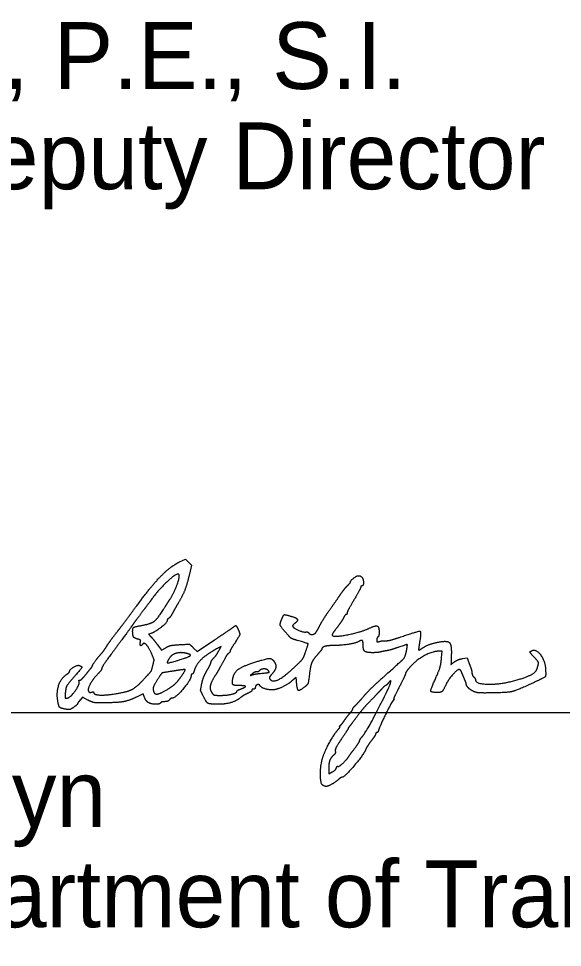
# Model space of a CAD drawing. Extents: x 0 to 34, y 0 to 22.
# Drawn here: x 25.662 to 26.8, y 6.888 to 8.834 of the extents above; entities that cross this region are included whole.
import ezdxf

# ---------------------------------------------------------------- set-up
doc = ezdxf.new("R2010")
doc.units = 0
for name, color, linetype in [('Default', 7, 'Continuous'), ('SH_Data', 7, 'Continuous'), ('SH_Text', 7, 'Continuous')]:
    doc.layers.add(name, color=color, linetype=linetype)

msp = doc.modelspace()

# ---------------------------------------------------------------- linework, layer by layer
at = {"layer": 'Default'}
for points in [[(25.9984, 7.6954), (26.011, 7.7013), (26.0174, 7.6949), (26.0237, 7.6885), (26.0193, 7.6699)], [(25.9385, 7.5455), (25.9335, 7.5439), (25.9386, 7.5387)], [(26.0274, 7.5158), (26.0356, 7.5081), (26.0718, 7.5322)], [(25.9523, 7.5221), (25.9608, 7.5105), (25.9696, 7.5158)], [(26.0813, 7.5105), (26.0858, 7.5184), (26.0803, 7.5155)], [(26.5472, 7.4946), (26.5487, 7.5084), (26.5408, 7.5084)], [(26.591, 7.493), (26.6007, 7.4945), (26.6058, 7.4809)], [(26.2431, 7.4468), (26.2424, 7.4536), (26.2365, 7.4485)], [(25.9255, 7.4112), (25.9221, 7.4192), (25.9083, 7.4124)], [(25.8068, 7.4062), (25.7953, 7.4119), (25.7903, 7.4061)], [(26.3108, 7.2607), (26.3108, 7.2513), (26.3184, 7.2556)]]:
    msp.add_lwpolyline(points, dxfattribs=at)
for points in [[(25.9088, 7.6035), (25.9385, 7.6441), (25.9803, 7.687), (25.9984, 7.6954)], [(25.9969, 7.6696), (25.9933, 7.6733), (25.9547, 7.6376), (25.9394, 7.6163)], [(25.9786, 7.6176), (25.9881, 7.6325), (26, 7.6665), (25.9969, 7.6696)], [(26.0193, 7.6699), (26.0143, 7.6487), (26.0052, 7.6251), (25.9957, 7.6092)], [(26.3564, 7.6535), (26.3564, 7.6563), (26.3696, 7.6666), (26.3733, 7.6667)], [(26.3733, 7.6667), (26.3754, 7.6667), (26.3784, 7.6655), (26.3799, 7.6639)], [(26.3498, 7.6454), (26.3535, 7.649), (26.3564, 7.6527), (26.3564, 7.6535)], [(26.3799, 7.6639), (26.3834, 7.6604), (26.3838, 7.6452), (26.3804, 7.6452)], [(26.3144, 7.5972), (26.3224, 7.6084), (26.3321, 7.6223), (26.336, 7.6282)], [(26.336, 7.6282), (26.34, 7.634), (26.3462, 7.6418), (26.3498, 7.6454)], [(26.378, 7.6427), (26.378, 7.6413), (26.3715, 7.6292), (26.3636, 7.6158)], [(26.3804, 7.6452), (26.3791, 7.6452), (26.378, 7.644), (26.378, 7.6427)], [(25.9394, 7.6163), (25.9358, 7.6113), (25.9263, 7.5986), (25.9184, 7.5881)], [(25.9681, 7.6009), (25.9714, 7.6061), (25.9761, 7.6136), (25.9786, 7.6176)], [(25.9957, 7.6092), (25.9922, 7.6032), (25.987, 7.5941), (25.9842, 7.5888)], [(26.3636, 7.6158), (26.3557, 7.6024), (26.3492, 7.59), (26.3492, 7.5883)], [(25.8687, 7.5501), (25.8776, 7.5614), (25.8956, 7.5855), (25.9088, 7.6035)], [(25.9183, 7.5623), (25.9389, 7.566), (25.953, 7.5769), (25.9681, 7.6009)], [(25.9842, 7.5888), (25.9813, 7.5835), (25.9775, 7.5783), (25.9757, 7.5773)], [(26.293, 7.5636), (26.2969, 7.5708), (26.3065, 7.586), (26.3144, 7.5972)], [(26.3492, 7.5883), (26.3492, 7.5866), (26.3483, 7.5852), (26.3472, 7.5852)], [(25.9184, 7.5881), (25.9105, 7.5777), (25.9024, 7.5667), (25.9004, 7.5637)], [(25.9724, 7.5718), (25.9724, 7.5681), (25.9467, 7.5481), (25.9385, 7.5455)], [(25.9757, 7.5773), (25.9739, 7.5762), (25.9724, 7.5738), (25.9724, 7.5718)], [(26.2222, 7.546), (26.2106, 7.5591), (26.2084, 7.5658), (26.2124, 7.5754)], [(26.2124, 7.5754), (26.2161, 7.5845), (26.2192, 7.5855), (26.232, 7.5817)], [(26.232, 7.5817), (26.2439, 7.5782), (26.2468, 7.572), (26.2391, 7.5662)], [(26.342, 7.5786), (26.3402, 7.5749), (26.3341, 7.5659), (26.3284, 7.5584)], [(26.3472, 7.5852), (26.3461, 7.5852), (26.3438, 7.5822), (26.342, 7.5786)], [(25.8471, 7.5207), (25.8501, 7.5255), (25.8598, 7.5388), (25.8687, 7.5501)], [(25.9004, 7.5637), (25.8984, 7.5607), (25.8831, 7.5398), (25.8663, 7.5171)], [(25.9004, 7.5501), (25.9004, 7.557), (25.9045, 7.5598), (25.9183, 7.5623)], [(25.9114, 7.5337), (25.9042, 7.5355), (25.9004, 7.5412), (25.9004, 7.5501)], [(26.0718, 7.5322), (26.0917, 7.5455), (26.1093, 7.5574), (26.1109, 7.5588)], [(26.1109, 7.5588), (26.1155, 7.5625), (26.1178, 7.5617), (26.1208, 7.5551)], [(26.1208, 7.5551), (26.1252, 7.5454), (26.1243, 7.5413), (26.114, 7.5255)], [(26.2391, 7.5662), (26.2364, 7.5641), (26.2349, 7.5613), (26.2359, 7.5599)], [(26.2359, 7.5599), (26.2386, 7.5561), (26.2585, 7.5479), (26.2631, 7.5487)], [(26.2838, 7.5474), (26.2851, 7.549), (26.2892, 7.5563), (26.293, 7.5636)], [(26.3284, 7.5584), (26.3227, 7.5509), (26.318, 7.5437), (26.318, 7.5423)], [(26.318, 7.5423), (26.318, 7.537), (26.3776, 7.548), (26.3956, 7.5565)], [(26.3956, 7.5565), (26.4086, 7.5627), (26.4164, 7.5596), (26.4164, 7.5482)], [(26.4588, 7.5375), (26.4991, 7.5513), (26.5051, 7.5497), (26.5009, 7.5258)], [(25.9165, 7.5275), (25.9174, 7.531), (25.9162, 7.5325), (25.9114, 7.5337)], [(25.9386, 7.5387), (25.9414, 7.5359), (25.9476, 7.5284), (25.9523, 7.5221)], [(26.2456, 7.5309), (26.2349, 7.534), (26.2299, 7.5371), (26.2222, 7.546)], [(26.2624, 7.5071), (26.2681, 7.5239), (26.2677, 7.5245), (26.2456, 7.5309)], [(26.2631, 7.5487), (26.2653, 7.5491), (26.2679, 7.5483), (26.2688, 7.5469)], [(26.2688, 7.5469), (26.2709, 7.5434), (26.2809, 7.5437), (26.2838, 7.5474)], [(26.3828, 7.523), (26.3828, 7.5304), (26.3791, 7.5319), (26.3714, 7.5277)], [(26.414, 7.5384), (26.4127, 7.5376), (26.4116, 7.5347), (26.4116, 7.5321)], [(26.4116, 7.5321), (26.4116, 7.5282), (26.4126, 7.5276), (26.417, 7.529)], [(26.4164, 7.5482), (26.4164, 7.5436), (26.4153, 7.5392), (26.414, 7.5384)], [(26.417, 7.529), (26.42, 7.5299), (26.4258, 7.5306), (26.43, 7.5304)], [(26.43, 7.5304), (26.4341, 7.5303), (26.4471, 7.5334), (26.4588, 7.5375)], [(25.8308, 7.4988), (25.8374, 7.5062), (25.8417, 7.5119), (25.8471, 7.5207)], [(25.8663, 7.5171), (25.8495, 7.4945), (25.8357, 7.4744), (25.8356, 7.4724)], [(25.9208, 7.5227), (25.9184, 7.5188), (25.9152, 7.5224), (25.9165, 7.5275)], [(25.9396, 7.5041), (25.9335, 7.5178), (25.9237, 7.5274), (25.9208, 7.5227)], [(25.9696, 7.5158), (25.9761, 7.5196), (25.9837, 7.5213), (25.9988, 7.5222)], [(25.9988, 7.5222), (26.0192, 7.5234), (26.0193, 7.5233), (26.0274, 7.5158)], [(26.0803, 7.5155), (26.0569, 7.503), (26.0341, 7.4823), (26.03, 7.4698)], [(26.0685, 7.4924), (26.074, 7.4983), (26.0765, 7.5019), (26.0813, 7.5105)], [(26.114, 7.5255), (26.1087, 7.5173), (26.1044, 7.5097), (26.1044, 7.5086)], [(26.2964, 7.5132), (26.2964, 7.5123), (26.2922, 7.5069), (26.2871, 7.5012)], [(26.3207, 7.5204), (26.3092, 7.5204), (26.2964, 7.5166), (26.2964, 7.5132)], [(26.3714, 7.5277), (26.3658, 7.5248), (26.3356, 7.5204), (26.3207, 7.5204)], [(26.4021, 7.5054), (26.3897, 7.5054), (26.3828, 7.5117), (26.3828, 7.523)], [(26.4292, 7.4579), (26.4647, 7.4894), (26.4716, 7.4976), (26.474, 7.5108)], [(26.4534, 7.5155), (26.4456, 7.5128), (26.436, 7.5101), (26.432, 7.5094)], [(26.474, 7.5108), (26.4761, 7.5223), (26.4744, 7.5227), (26.4534, 7.5155)], [(26.5009, 7.5258), (26.4996, 7.5182), (26.4989, 7.5116), (26.4993, 7.5111)], [(26.4993, 7.5111), (26.4998, 7.5106), (26.5032, 7.5124), (26.5069, 7.515)], [(26.5069, 7.515), (26.5141, 7.52), (26.5324, 7.5263), (26.546, 7.5285)], [(26.546, 7.5285), (26.5607, 7.5308), (26.5683, 7.5204), (26.5675, 7.4991)], [(26.7367, 7.5099), (26.7453, 7.5132), (26.7637, 7.4882), (26.7647, 7.472)], [(25.8164, 7.4784), (25.8164, 7.48), (25.8256, 7.493), (25.8308, 7.4988)], [(25.9429, 7.4796), (25.9455, 7.4894), (25.9452, 7.4916), (25.9396, 7.5041)], [(25.9781, 7.495), (25.971, 7.4842), (25.9756, 7.4834), (26, 7.4909)], [(26.0106, 7.5045), (25.9998, 7.5066), (25.9824, 7.5015), (25.9781, 7.495)], [(26, 7.4909), (26.0193, 7.4968), (26.0232, 7.5019), (26.0106, 7.5045)], [(26.0645, 7.4853), (26.0648, 7.4871), (26.0666, 7.4902), (26.0685, 7.4924)], [(26.094, 7.4943), (26.0859, 7.4789), (26.0781, 7.4652), (26.0719, 7.4554)], [(26.1009, 7.5036), (26.0989, 7.502), (26.0958, 7.4978), (26.094, 7.4943)], [(26.1044, 7.5086), (26.1044, 7.5075), (26.1028, 7.5052), (26.1009, 7.5036)], [(26.1478, 7.4826), (26.1796, 7.4932), (26.1931, 7.4936), (26.1981, 7.4842)], [(26.2441, 7.4798), (26.2545, 7.4898), (26.2587, 7.496), (26.2624, 7.5071)], [(26.2871, 7.5012), (26.2786, 7.4917), (26.2729, 7.4791), (26.2713, 7.4664)], [(26.4188, 7.5068), (26.4155, 7.506), (26.408, 7.5054), (26.4021, 7.5054)], [(26.432, 7.5094), (26.4281, 7.5088), (26.4221, 7.5076), (26.4188, 7.5068)], [(26.5408, 7.5084), (26.5282, 7.5084), (26.4944, 7.49), (26.4822, 7.4764)], [(26.5325, 7.4467), (26.5415, 7.4666), (26.5456, 7.4798), (26.5472, 7.4946)], [(26.5675, 7.4991), (26.5669, 7.4807), (26.5667, 7.481), (26.5745, 7.4865)], [(26.5745, 7.4865), (26.5782, 7.4892), (26.5857, 7.4921), (26.591, 7.493)], [(26.7376, 7.4998), (26.7323, 7.5054), (26.7321, 7.5081), (26.7367, 7.5099)], [(26.7467, 7.4707), (26.7507, 7.4825), (26.7492, 7.4874), (26.7376, 7.4998)], [(25.7685, 7.4664), (25.7685, 7.4701), (25.7853, 7.4801), (25.789, 7.4786)], [(25.789, 7.4786), (25.795, 7.4763), (25.7927, 7.4715), (25.7784, 7.4555)], [(25.8019, 7.4592), (25.8073, 7.4658), (25.8127, 7.4725), (25.814, 7.4741)], [(25.814, 7.4741), (25.8153, 7.4757), (25.8164, 7.4776), (25.8164, 7.4784)], [(25.8356, 7.4724), (25.8355, 7.4704), (25.8322, 7.4656), (25.8282, 7.4616)], [(25.9232, 7.4491), (25.9393, 7.4667), (25.9396, 7.4672), (25.9429, 7.4796)], [(26.0561, 7.4683), (26.0605, 7.4759), (26.0643, 7.4836), (26.0645, 7.4853)], [(26.1102, 7.4516), (26.1123, 7.4628), (26.1285, 7.4762), (26.1478, 7.4826)], [(26.1839, 7.4684), (26.1811, 7.4718), (26.1677, 7.471), (26.1655, 7.4673)], [(26.1871, 7.451), (26.1925, 7.4423), (26.2192, 7.4558), (26.2441, 7.4798)], [(26.1981, 7.4842), (26.2014, 7.4781), (26.1979, 7.4668), (26.1905, 7.4589)], [(26.4822, 7.4764), (26.4764, 7.4699), (26.4716, 7.4634), (26.4716, 7.4618)], [(26.6058, 7.4809), (26.6085, 7.4735), (26.6108, 7.4654), (26.6108, 7.4629)], [(26.7647, 7.472), (26.7657, 7.4566), (26.763, 7.4535), (26.7396, 7.4425)], [(25.7436, 7.4047), (25.7406, 7.4233), (25.7514, 7.4533), (25.7638, 7.461)], [(25.7784, 7.4555), (25.7647, 7.4404), (25.7597, 7.4302), (25.7591, 7.4164)], [(25.7638, 7.461), (25.7663, 7.4626), (25.7684, 7.465), (25.7685, 7.4664)], [(25.7896, 7.4479), (25.791, 7.4475), (25.7966, 7.4526), (25.8019, 7.4592)], [(25.8282, 7.4616), (25.8184, 7.452), (25.806, 7.4299), (25.8078, 7.4252)], [(25.9808, 7.4661), (25.9631, 7.4636), (25.961, 7.4624), (25.9537, 7.4512)], [(25.9733, 7.4285), (25.9845, 7.4354), (25.9955, 7.446), (26.0032, 7.4571)], [(25.9982, 7.4688), (25.9926, 7.4679), (25.9848, 7.4667), (25.9808, 7.4661)], [(26.0228, 7.4574), (26.0227, 7.4488), (25.9896, 7.41), (25.9824, 7.41)], [(26.0032, 7.4571), (26.011, 7.4685), (26.0101, 7.4707), (25.9982, 7.4688)], [(26.0248, 7.4604), (26.0237, 7.4604), (26.0228, 7.459), (26.0228, 7.4574)], [(26.03, 7.4698), (26.0283, 7.4646), (26.0259, 7.4604), (26.0248, 7.4604)], [(26.0452, 7.4404), (26.0467, 7.4481), (26.0517, 7.4606), (26.0561, 7.4683)], [(26.0719, 7.4554), (26.064, 7.4428), (26.0617, 7.4276), (26.0668, 7.4208)], [(26.1511, 7.4614), (26.1465, 7.4576), (26.1465, 7.4576), (26.1512, 7.4593)], [(26.1599, 7.4652), (26.1576, 7.4652), (26.1536, 7.4635), (26.1511, 7.4614)], [(26.1512, 7.4593), (26.1539, 7.4602), (26.1614, 7.4614), (26.168, 7.462)], [(26.1655, 7.4673), (26.1647, 7.4661), (26.1622, 7.4652), (26.1599, 7.4652)], [(26.168, 7.462), (26.1848, 7.4636), (26.1872, 7.4645), (26.1839, 7.4684)], [(26.1905, 7.4589), (26.1878, 7.4559), (26.1862, 7.4524), (26.1871, 7.451)], [(26.2713, 7.4664), (26.2684, 7.4439), (26.2667, 7.4384), (26.261, 7.4339)], [(26.3851, 7.4151), (26.3924, 7.4235), (26.4122, 7.4427), (26.4292, 7.4579)], [(26.4716, 7.4618), (26.4716, 7.4602), (26.4657, 7.4474), (26.4584, 7.4333)], [(26.584, 7.47), (26.5797, 7.47), (26.5615, 7.4495), (26.5568, 7.4393)], [(26.5896, 7.4634), (26.5881, 7.467), (26.5856, 7.47), (26.584, 7.47)], [(26.5956, 7.4492), (26.5938, 7.4534), (26.5911, 7.4597), (26.5896, 7.4634)], [(26.6108, 7.4629), (26.6108, 7.4604), (26.6124, 7.4567), (26.6144, 7.4547)], [(26.6144, 7.4547), (26.6164, 7.4527), (26.618, 7.45), (26.618, 7.4487)], [(26.6979, 7.4464), (26.7215, 7.4526), (26.7445, 7.464), (26.7467, 7.4707)], [(25.764, 7.4104), (25.7703, 7.4114), (25.7904, 7.4398), (25.7884, 7.445)], [(25.7884, 7.445), (25.7877, 7.447), (25.7882, 7.4483), (25.7896, 7.4479)], [(25.8667, 7.4197), (25.8894, 7.4234), (25.9091, 7.4336), (25.9232, 7.4491)], [(25.9537, 7.4512), (25.9455, 7.4386), (25.9424, 7.4287), (25.9446, 7.4229)], [(26.0472, 7.4164), (26.0427, 7.4255), (26.0425, 7.4277), (26.0452, 7.4404)], [(26.1238, 7.4364), (26.1123, 7.4364), (26.1082, 7.4409), (26.1102, 7.4516)], [(26.1271, 7.4295), (26.1374, 7.4332), (26.1359, 7.4364), (26.1238, 7.4364)], [(26.1572, 7.4325), (26.1572, 7.4307), (26.1556, 7.4292), (26.1536, 7.4292)], [(26.1667, 7.4365), (26.1647, 7.4398), (26.1572, 7.4367), (26.1572, 7.4325)], [(26.198, 7.428), (26.1894, 7.4265), (26.1696, 7.4318), (26.1667, 7.4365)], [(26.2365, 7.4485), (26.2272, 7.4403), (26.2072, 7.4297), (26.198, 7.428)], [(26.261, 7.4339), (26.2493, 7.4247), (26.2449, 7.4278), (26.2431, 7.4468)], [(26.3825, 7.3313), (26.3902, 7.34), (26.4434, 7.4438), (26.4413, 7.4459)], [(26.4299, 7.4364), (26.4291, 7.4364), (26.4251, 7.4329), (26.4211, 7.4286)], [(26.4356, 7.4418), (26.4332, 7.4388), (26.4306, 7.4364), (26.4299, 7.4364)], [(26.4413, 7.4459), (26.4406, 7.4466), (26.438, 7.4447), (26.4356, 7.4418)], [(26.4584, 7.4333), (26.4511, 7.4191), (26.446, 7.4076), (26.447, 7.4075)], [(26.5398, 7.422), (26.5253, 7.422), (26.5237, 7.4274), (26.5325, 7.4467)], [(26.5568, 7.4393), (26.551, 7.4269), (26.5462, 7.422), (26.5398, 7.422)], [(26.5989, 7.4396), (26.5989, 7.4407), (26.5974, 7.4451), (26.5956, 7.4492)], [(26.6146, 7.424), (26.6075, 7.4274), (26.5991, 7.4358), (26.5989, 7.4396)], [(26.618, 7.4487), (26.618, 7.4402), (26.6686, 7.4387), (26.6979, 7.4464)], [(26.7396, 7.4425), (26.7048, 7.4262), (26.6838, 7.4214), (26.6444, 7.421)], [(25.7591, 7.4164), (25.7589, 7.4108), (25.7597, 7.4098), (25.764, 7.4104)], [(25.8078, 7.4252), (25.8087, 7.4228), (25.8111, 7.4219), (25.8141, 7.4227)], [(25.8141, 7.4227), (25.8167, 7.4234), (25.8188, 7.423), (25.8188, 7.4219)], [(25.8188, 7.4219), (25.8188, 7.4173), (25.8445, 7.4161), (25.8667, 7.4197)], [(25.9446, 7.4229), (25.9466, 7.4177), (25.9602, 7.4203), (25.9733, 7.4285)], [(26.0789, 7.3973), (26.0614, 7.3974), (26.0544, 7.4016), (26.0472, 7.4164)], [(26.0668, 7.4208), (26.0697, 7.417), (26.0732, 7.416), (26.0844, 7.416)], [(26.0844, 7.416), (26.0984, 7.416), (26.1188, 7.4211), (26.1188, 7.4246)], [(26.1188, 7.4246), (26.1188, 7.4256), (26.1225, 7.4278), (26.1271, 7.4295)], [(26.1446, 7.4218), (26.1373, 7.4185), (26.1297, 7.414), (26.1254, 7.4105)], [(26.15, 7.4267), (26.15, 7.4254), (26.1476, 7.4232), (26.1446, 7.4218)], [(26.1536, 7.4292), (26.1516, 7.4292), (26.15, 7.4281), (26.15, 7.4267)], [(26.3667, 7.3947), (26.3696, 7.3975), (26.3779, 7.4067), (26.3851, 7.4151)], [(26.4211, 7.4286), (26.417, 7.4243), (26.4064, 7.4132), (26.3976, 7.4039)], [(26.6444, 7.421), (26.6295, 7.4208), (26.6192, 7.4219), (26.6146, 7.424)], [(25.7601, 7.387), (25.7493, 7.389), (25.7454, 7.3931), (25.7436, 7.4047)], [(25.7852, 7.3986), (25.7852, 7.3976), (25.7814, 7.3942), (25.7769, 7.3911)], [(25.7903, 7.4061), (25.7875, 7.4029), (25.7852, 7.3995), (25.7852, 7.3986)], [(25.8376, 7.4004), (25.822, 7.4004), (25.8161, 7.4015), (25.8068, 7.4062)], [(25.9083, 7.4124), (25.8927, 7.4046), (25.8675, 7.4004), (25.8376, 7.4004)], [(25.9337, 7.4006), (25.931, 7.402), (25.9273, 7.4068), (25.9255, 7.4112)], [(25.9592, 7.4004), (25.9572, 7.3972), (25.9398, 7.3973), (25.9337, 7.4006)], [(25.9675, 7.4028), (25.9638, 7.4028), (25.96, 7.4017), (25.9592, 7.4004)], [(25.9772, 7.4064), (25.9756, 7.4044), (25.9712, 7.4028), (25.9675, 7.4028)], [(25.9824, 7.41), (25.9812, 7.41), (25.9789, 7.4084), (25.9772, 7.4064)], [(26.1254, 7.4105), (26.1177, 7.4041), (26.0934, 7.3972), (26.0789, 7.3973)], [(26.3613, 7.3875), (26.3613, 7.3886), (26.3637, 7.3919), (26.3667, 7.3947)], [(26.3976, 7.4039), (26.3888, 7.3947), (26.3789, 7.3834), (26.3756, 7.379)], [(26.4462, 7.4057), (26.4436, 7.4039), (26.4183, 7.3529), (26.4154, 7.3434)], [(26.447, 7.4075), (26.448, 7.4075), (26.4477, 7.4067), (26.4462, 7.4057)], [(25.7769, 7.3911), (25.7703, 7.3866), (25.7667, 7.3858), (25.7601, 7.387)], [(26.3444, 7.3644), (26.3464, 7.3674), (26.351, 7.3734), (26.3546, 7.3777)], [(26.3756, 7.379), (26.3675, 7.368), (26.357, 7.3542), (26.3541, 7.3507)], [(26.3546, 7.3777), (26.3583, 7.3819), (26.3612, 7.3863), (26.3613, 7.3875)], [(26.3366, 7.3544), (26.3389, 7.3568), (26.3424, 7.3613), (26.3444, 7.3644)], [(26.3006, 7.292), (26.3065, 7.3068), (26.3237, 7.3367), (26.3308, 7.3446)], [(26.3308, 7.3446), (26.3335, 7.3475), (26.3349, 7.35), (26.334, 7.35)], [(26.334, 7.35), (26.3332, 7.35), (26.3343, 7.352), (26.3366, 7.3544)], [(26.3516, 7.3468), (26.3516, 7.3462), (26.3453, 7.3363), (26.3376, 7.3247)], [(26.3541, 7.3507), (26.3527, 7.3491), (26.3516, 7.3473), (26.3516, 7.3468)], [(26.4092, 7.3355), (26.4092, 7.3341), (26.405, 7.3273), (26.3997, 7.3204)], [(26.4115, 7.338), (26.4102, 7.338), (26.4092, 7.3368), (26.4092, 7.3355)], [(26.4154, 7.3434), (26.4145, 7.3404), (26.4127, 7.338), (26.4115, 7.338)], [(26.3376, 7.3247), (26.3289, 7.3116), (26.3239, 7.3019), (26.3246, 7.2992)], [(26.3654, 7.3052), (26.371, 7.3125), (26.3756, 7.3197), (26.3756, 7.321)], [(26.3756, 7.321), (26.3756, 7.3223), (26.3787, 7.327), (26.3825, 7.3313)], [(26.3997, 7.3204), (26.3945, 7.3135), (26.3894, 7.3055), (26.3883, 7.3027)], [(26.3246, 7.2992), (26.3253, 7.2966), (26.3237, 7.293), (26.321, 7.2906)], [(26.3883, 7.3027), (26.3847, 7.2929), (26.3435, 7.2444), (26.3388, 7.2444)], [(26.3528, 7.2879), (26.3541, 7.29), (26.3598, 7.2978), (26.3654, 7.3052)], [(26.2988, 7.2275), (26.2929, 7.2313), (26.2941, 7.2756), (26.3006, 7.292)], [(26.321, 7.2906), (26.315, 7.2854), (26.3108, 7.273), (26.3108, 7.2607)], [(26.33, 7.2672), (26.3319, 7.266), (26.3486, 7.2811), (26.3528, 7.2879)], [(26.3184, 7.2556), (26.3225, 7.258), (26.3264, 7.2619), (26.327, 7.2641)], [(26.327, 7.2641), (26.3277, 7.2664), (26.329, 7.2678), (26.33, 7.2672)], [(26.3314, 7.2398), (26.3252, 7.2341), (26.3092, 7.2252), (26.3053, 7.2252)], [(26.3388, 7.2444), (26.3375, 7.2444), (26.3341, 7.2423), (26.3314, 7.2398)], [(26.3053, 7.2252), (26.3037, 7.2252), (26.3008, 7.2263), (26.2988, 7.2275)]]:
    msp.add_open_spline(points, degree=2, dxfattribs=at)
at = {"layer": 'SH_Data'}
msp.add_line((24.5131, 7.3802), (28.0131, 7.3802), dxfattribs=at)

# ---------------------------------------------------------------- texts
at = {"layer": 'SH_Text'}
for s, p in [('Pat McColley, P.E., S.I.', (24.5279, 8.6862)), ('District       Deputy Director', (24.5279, 8.4762)), ('Pamela Boratyn', (24.5131, 7.1402)), ('Director, Department of Transportation', (24.5131, 6.9302))]:
    msp.add_text(s, height=0.14, dxfattribs=at).set_placement(p)

doc.saveas('drawing.dxf')
